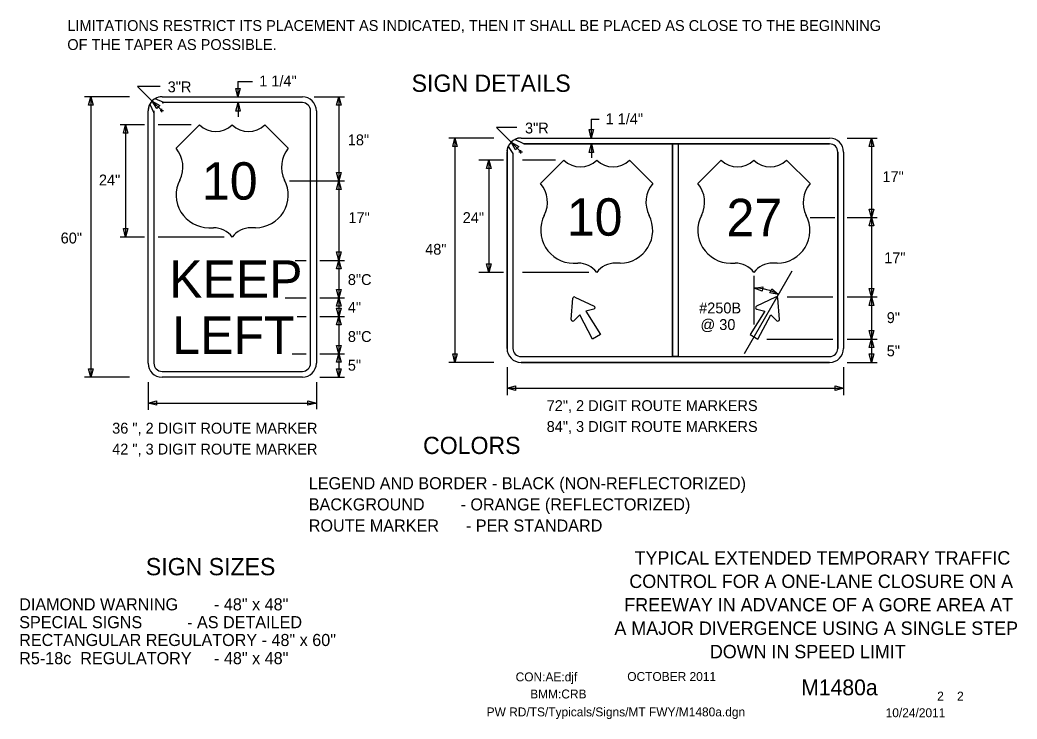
# Model space of a CAD drawing. Extents: x 16284 to 18468, y 5417 to 6974.
# Drawn here: x 17775 to 18468, y 5932 to 6418 of the extents above; entities that cross this region are included whole.
import ezdxf

# ---------------------------------------------------------------- set-up
doc = ezdxf.new("R2010")
doc.units = 0
for name, color, linetype in [('BORDER', 7, 'Continuous'), ('BORDER_SIGNAL_WO', 7, 'Continuous'), ('TRAFFIC_SIGNS_PR', 7, 'Continuous'), ('TYPICAL_EX', 7, 'Continuous'), ('TYPICAL_TEXT_DIMEN_PR', 7, 'Continuous')]:
    doc.layers.add(name, color=color, linetype=linetype)

msp = doc.modelspace()

# ---------------------------------------------------------------- linework, layer by layer
at = {"layer": 'TRAFFIC_SIGNS_PR'}
for p, q in [((17873.92, 6364.59), (17971.42, 6364.59)), ((17866.33, 6360.97), (17865.33, 6359.46)), ((17865.36, 6359.39), (17868.23, 6353.35)), ((17875.12, 6360.53), (17869.02, 6363.27)), ((17971.42, 6360.53), (17873.92, 6360.53)), ((17864.17, 6179.34), (17864.17, 6354.84)), ((17868.23, 6354.84), (17868.23, 6179.34)), ((17977.1, 6179.34), (17977.1, 6354.84)), ((17981.17, 6354.84), (17981.17, 6179.34)), ((18123.44, 6335.89), (18337.94, 6335.89)), ((18123.44, 6335.89), (18337.94, 6335.89)), ((18114.61, 6330.15), (18117.74, 6325.11)), ((18125.39, 6331.84), (18119.16, 6334.86)), ((18125.38, 6331.83), (18228.66, 6331.83)), ((18337.94, 6331.83), (18125.38, 6331.83)), ((18228.66, 6331.83), (18228.66, 6183.95)), ((18232.72, 6331.83), (18232.72, 6183.95)), ((18232.72, 6331.83), (18337.94, 6331.83)), ((18113.69, 6326.14), (18113.69, 6189.64)), ((18113.69, 6189.64), (18113.69, 6326.14)), ((18117.75, 6325.09), (18117.75, 6189.64)), ((18117.75, 6325.09), (18117.75, 6189.64)), ((18343.62, 6326.14), (18343.62, 6280.39)), ((18343.63, 6189.64), (18343.63, 6326.14)), ((18347.69, 6326.14), (18347.69, 6189.64)), ((18347.69, 6326.14), (18347.69, 6189.64)), ((18343.62, 6280.39), (18343.62, 6189.64)), ((18160.95, 6225.34), (18174.27, 6218.98)), ((18300.42, 6225.34), (18287.11, 6218.98)), ((18158.29, 6209.75), (18159.44, 6224.47)), ((18303.08, 6209.75), (18301.94, 6224.47)), ((18123.44, 6183.95), (18337.94, 6183.95)), ((18123.44, 6179.89), (18337.94, 6179.89)), ((18337.94, 6179.89), (18123.44, 6179.89)), ((17873.92, 6173.65), (17971.42, 6173.65)), ((17971.42, 6169.59), (17873.92, 6169.59))]:
    msp.add_line(p, q, dxfattribs=at)
for points in [[(18125.38, 6331.83), (18125.36, 6331.84)], [(18117.74, 6325.11), (18117.75, 6325.09)], [(18174.1, 6217.01), (18168.38, 6215.43), (18178.6, 6199.26), (18173.2, 6196.14), (18164.31, 6213.08), (18160.08, 6208.91)], [(18287.27, 6217.01), (18292.99, 6215.43), (18282.78, 6199.26), (18288.17, 6196.14), (18297.07, 6213.08), (18301.29, 6208.91)]]:
    msp.add_lwpolyline(points, dxfattribs=at)
msp.add_lwpolyline([(18228.66, 6331.83), (18232.72, 6331.83), (18232.72, 6183.95), (18228.66, 6183.95)], close=True, dxfattribs=at)
for centre, radius, start, end in [((17873.92, 6354.84), 9.75, 90, 180), ((17873.33, 6357.01), 7.6, 85.58319, 124.53531), ((17971.42, 6354.84), 9.75, 0, 90), ((17871.2, 6355.43), 7.06, 145.86811, 184.82317), ((17874.52, 6364.95), 4.47, 262.2432, 277.7568), ((17971.42, 6354.84), 5.69, 0, 90), ((17862.77, 6354.1), 5.51, 352.24294, 7.75653), ((18123.44, 6326.14), 9.75, 90, 180), ((18123.44, 6326.14), 9.75, 90, 180), ((18122.76, 6329.33), 6.6, 84.11162, 123.06374), ((18337.94, 6326.14), 9.75, 0, 90), ((18337.94, 6326.14), 9.75, 0, 90), ((18119.82, 6326.85), 6.17, 147.60925, 186.56283), ((18124.38, 6339.01), 7.24, 277.81035, 278.05403), ((18337.94, 6326.14), 5.69, 0, 89.99421), ((18337.94, 6326.14), 5.69, 0, 90), ((18160.5, 6224.38), 1.06, 64.48226, 175.51774), ((18300.88, 6224.38), 1.06, 4.48226, 115.51774), ((18173.81, 6218.02), 1.06, 285.9885, 64.48226), ((18287.56, 6218.02), 1.06, 115.51774, 254.0115), ((18159.35, 6209.67), 1.06, 175.51775, 314.01151), ((18302.03, 6209.67), 1.06, 225.98849, 4.48225), ((18123.44, 6189.64), 9.75, 180, 270), ((18123.44, 6189.64), 9.75, 180, 270), ((18123.44, 6189.64), 5.69, 180, 270), ((18123.44, 6189.64), 5.69, 180, 270), ((18337.94, 6189.64), 9.75, 270, 0), ((18337.94, 6189.64), 5.69, 270, 0), ((18337.94, 6189.64), 9.75, 270, 0), ((18337.94, 6189.64), 5.69, 270, 0), ((17873.92, 6179.34), 9.75, 180, 270), ((17873.92, 6179.34), 5.69, 180, 270), ((17971.42, 6179.34), 5.69, 270, 0), ((17971.42, 6179.34), 9.75, 270, 0)]:
    msp.add_arc(centre, radius, start, end, dxfattribs=at)
at = {"layer": 'TYPICAL_EX'}
for p, q in [((17883.67, 6328.84), (17899.92, 6345.09)), ((17961.67, 6328.84), (17945.42, 6345.09)), ((18137.05, 6304.23), (18153.3, 6320.48)), ((18215.05, 6304.23), (18198.8, 6320.48)), ((18246.33, 6304.23), (18262.58, 6320.48)), ((18324.33, 6304.23), (18308.08, 6320.48)), ((17906.39, 6273.55), (17909.64, 6273.55)), ((17938.94, 6273.55), (17935.69, 6273.55)), ((18159.78, 6248.94), (18163.03, 6248.94)), ((18192.32, 6248.94), (18189.07, 6248.94)), ((18269.05, 6248.94), (18272.3, 6248.94)), ((18301.6, 6248.94), (18298.35, 6248.94))]:
    msp.add_line(p, q, dxfattribs=at)
for centre, radius, start, end in [((17911.29, 6356.93), 16.42, 226.14041, 313.85958), ((17934.04, 6356.93), 16.42, 226.14042, 313.85959), ((17868.26, 6315.83), 20.16, 333.09768, 40.19361), ((17977.07, 6315.83), 20.16, 139.80639, 206.90233), ((18164.68, 6332.32), 16.42, 226.14041, 313.85958), ((18187.42, 6332.32), 16.42, 226.14042, 313.85959), ((18273.95, 6332.32), 16.42, 226.14041, 313.85958), ((18296.7, 6332.32), 16.42, 226.14042, 313.85959), ((17906.43, 6296.27), 22.73, 152.6698, 269.90132), ((17938.9, 6296.27), 22.73, 270.09868, 27.3302), ((18121.65, 6291.22), 20.16, 333.09768, 40.19361), ((18230.45, 6291.22), 20.16, 139.80639, 206.90233), ((18230.93, 6291.22), 20.16, 333.09768, 40.19361), ((18339.73, 6291.22), 20.16, 139.80639, 206.90233), ((18159.82, 6271.66), 22.73, 152.6698, 269.90132), ((18192.28, 6271.66), 22.73, 270.09868, 27.3302), ((18269.09, 6271.66), 22.73, 152.6698, 269.90132), ((18301.56, 6271.66), 22.73, 270.09868, 27.3302), ((17909.68, 6257.27), 16.28, 37.1038, 90.13853), ((17935.65, 6257.27), 16.28, 89.86147, 142.8962), ((18163.07, 6232.66), 16.28, 37.1038, 90.13853), ((18189.03, 6232.66), 16.28, 89.86147, 142.8962), ((18272.35, 6232.66), 16.28, 37.1038, 90.13853), ((18298.31, 6232.66), 16.28, 89.86147, 142.8962)]:
    msp.add_arc(centre, radius, start, end, dxfattribs=at)
at = {"layer": 'TYPICAL_TEXT_DIMEN_PR'}
for p, q in [((17872.54, 6371.87), (17856.88, 6371.87)), ((17856.88, 6371.87), (17867.12, 6361.64)), ((17926.64, 6364.59), (17925.07, 6370.45)), ((17925.07, 6370.45), (17926.64, 6370.45)), ((17926.64, 6375.35), (17926.64, 6364.59)), ((17926.64, 6375.35), (17936.74, 6375.35)), ((17926.64, 6370.45), (17928.21, 6370.45)), ((17928.21, 6370.45), (17926.64, 6364.59)), ((17851.34, 6364.59), (17820.04, 6364.59)), ((17822.81, 6358.73), (17824.38, 6364.59)), ((17824.38, 6364.59), (17824.38, 6169.59)), ((17824.38, 6364.59), (17825.95, 6358.73)), ((17979.71, 6364.59), (18000.67, 6364.59)), ((17995.2, 6358.73), (17996.77, 6364.59)), ((17996.77, 6364.59), (17996.77, 6306.09)), ((17996.77, 6364.59), (17998.34, 6358.73)), ((17824.38, 6358.73), (17822.81, 6358.73)), ((17825.95, 6358.73), (17824.38, 6358.73)), ((17867.12, 6361.64), (17873.67, 6355.08)), ((17870.15, 6356.38), (17867.12, 6361.64)), ((17867.12, 6361.64), (17872.37, 6358.6)), ((17871.26, 6357.49), (17870.15, 6356.38)), ((17872.37, 6358.6), (17871.26, 6357.49)), ((17925.12, 6354.67), (17926.69, 6360.53)), ((17926.69, 6360.53), (17926.69, 6350.78)), ((17926.69, 6360.53), (17928.26, 6354.67)), ((17996.77, 6358.73), (17995.2, 6358.73)), ((17998.34, 6358.73), (17996.77, 6358.73)), ((17872.47, 6355.08), (17874.88, 6355.08)), ((17873.67, 6353.87), (17873.67, 6356.29)), ((17926.69, 6354.67), (17925.12, 6354.67)), ((17928.26, 6354.67), (17926.69, 6354.67)), ((17861.79, 6345.09), (17844.67, 6345.09)), ((17846.99, 6339.23), (17848.56, 6345.09)), ((17848.56, 6345.09), (17848.56, 6267.09)), ((17848.56, 6345.09), (17850.13, 6339.23)), ((17894.03, 6345.09), (17871.16, 6345.09)), ((18120.58, 6343.18), (18106.4, 6343.18)), ((18106.4, 6343.18), (18116.55, 6333.03)), ((18172.3, 6349.04), (18172.3, 6335.89)), ((18172.3, 6349.04), (18177.82, 6349.04)), ((17848.56, 6339.23), (17846.99, 6339.23)), ((17850.13, 6339.23), (17848.56, 6339.23)), ((18104.46, 6335.89), (18073.16, 6335.89)), ((18075.93, 6330.03), (18077.5, 6335.89)), ((18077.5, 6335.89), (18077.5, 6179.89)), ((18077.5, 6335.89), (18079.07, 6330.03)), ((18172.3, 6335.89), (18170.72, 6341.75)), ((18170.72, 6341.75), (18172.3, 6341.75)), ((18172.3, 6341.75), (18173.87, 6341.75)), ((18173.87, 6341.75), (18172.3, 6335.89)), ((18350.06, 6335.89), (18371.02, 6335.89)), ((18365.55, 6330.03), (18367.12, 6335.89)), ((18367.12, 6335.89), (18367.12, 6280.64)), ((18367.12, 6335.89), (18368.69, 6330.03)), ((18077.5, 6330.03), (18075.93, 6330.03)), ((18079.07, 6330.03), (18077.5, 6330.03)), ((18116.55, 6333.03), (18123.2, 6326.38)), ((18119.58, 6327.77), (18116.55, 6333.03)), ((18116.55, 6333.03), (18121.81, 6329.99)), ((18120.7, 6328.88), (18119.58, 6327.77)), ((18121.81, 6329.99), (18120.7, 6328.88)), ((18170.77, 6325.97), (18172.34, 6331.83)), ((18170.77, 6325.97), (18172.34, 6331.83)), ((18172.34, 6331.83), (18172.34, 6322.08)), ((18172.34, 6331.83), (18173.92, 6325.97)), ((18172.34, 6331.83), (18173.92, 6325.97)), ((18367.12, 6330.03), (18365.55, 6330.03)), ((18368.69, 6330.03), (18367.12, 6330.03)), ((18121.99, 6326.38), (18124.41, 6326.38)), ((18123.2, 6325.17), (18123.2, 6327.59)), ((18172.34, 6325.97), (18170.77, 6325.97)), ((18172.34, 6325.97), (18170.77, 6325.97)), ((18173.92, 6325.97), (18172.34, 6325.97)), ((18173.92, 6325.97), (18172.34, 6325.97)), ((18111.31, 6320.48), (18094.19, 6320.48)), ((18099.48, 6314.62), (18101.06, 6320.48)), ((18101.06, 6320.48), (18101.06, 6242.48)), ((18101.06, 6320.48), (18102.63, 6314.62)), ((18147.42, 6320.48), (18124.54, 6320.48)), ((17996.77, 6306.09), (17995.2, 6311.95)), ((17995.2, 6311.95), (17996.77, 6311.95)), ((17996.77, 6311.95), (17998.34, 6311.95)), ((17998.34, 6311.95), (17996.77, 6306.09)), ((18101.06, 6314.62), (18099.48, 6314.62)), ((18102.63, 6314.62), (18101.06, 6314.62)), ((17962.56, 6306.09), (18000.67, 6306.09)), ((17995.2, 6300.23), (17996.77, 6306.09)), ((17996.77, 6306.09), (17996.77, 6250.84)), ((17996.77, 6306.09), (17998.34, 6300.23)), ((17996.77, 6300.23), (17995.2, 6300.23)), ((17998.34, 6300.23), (17996.77, 6300.23)), ((18324.5, 6280.64), (18341.65, 6280.64)), ((18350.06, 6280.64), (18371.02, 6280.64)), ((18367.12, 6280.64), (18365.55, 6286.5)), ((18365.55, 6286.5), (18367.12, 6286.5)), ((18365.55, 6274.78), (18367.12, 6280.64)), ((18367.12, 6286.5), (18368.69, 6286.5)), ((18368.69, 6286.5), (18367.12, 6280.64)), ((18367.12, 6280.64), (18367.12, 6225.39)), ((18367.12, 6280.64), (18368.69, 6274.78)), ((18367.12, 6274.78), (18365.55, 6274.78)), ((18368.69, 6274.78), (18367.12, 6274.78)), ((17861.79, 6267.09), (17844.67, 6267.09)), ((17848.56, 6267.09), (17846.99, 6272.95)), ((17846.99, 6272.95), (17848.56, 6272.95)), ((17848.56, 6272.95), (17850.13, 6272.95)), ((17850.13, 6272.95), (17848.56, 6267.09)), ((17917.16, 6267.09), (17871.16, 6267.09)), ((17996.77, 6250.84), (17995.2, 6256.7)), ((17995.2, 6256.7), (17996.77, 6256.7)), ((17996.77, 6256.7), (17998.34, 6256.7)), ((17998.34, 6256.7), (17996.77, 6250.84)), ((17966.49, 6250.84), (17974.17, 6250.84)), ((17983.54, 6250.84), (18000.67, 6250.84)), ((17995.2, 6244.98), (17996.77, 6250.84)), ((17996.77, 6250.84), (17996.77, 6224.84)), ((17996.77, 6250.84), (17998.34, 6244.98)), ((18101.06, 6242.48), (18099.48, 6248.34)), ((18099.48, 6248.34), (18101.06, 6248.34)), ((18101.06, 6248.34), (18102.63, 6248.34)), ((18102.63, 6248.34), (18101.06, 6242.48)), ((17996.77, 6244.98), (17995.2, 6244.98)), ((17998.34, 6244.98), (17996.77, 6244.98)), ((18111.31, 6242.48), (18094.19, 6242.48)), ((18170.54, 6242.48), (18124.54, 6242.48)), ((18278.72, 6185.99), (18311.96, 6243.58)), ((18285.48, 6206.15), (18285.48, 6240.14)), ((18285.51, 6231.59), (18291.5, 6232.55)), ((18291.5, 6232.55), (18291.34, 6230.98)), ((17959.48, 6224.84), (17974.17, 6224.84)), ((17983.54, 6224.84), (18000.67, 6224.84)), ((17996.77, 6224.84), (17995.2, 6230.7)), ((17995.2, 6230.7), (17996.77, 6230.7)), ((17995.2, 6218.98), (17996.77, 6224.84)), ((17996.77, 6230.7), (17998.34, 6230.7)), ((17998.34, 6230.7), (17996.77, 6224.84)), ((17996.77, 6224.84), (17996.77, 6211.84)), ((17996.77, 6224.84), (17998.34, 6218.98)), ((18291.17, 6229.42), (18285.51, 6231.59)), ((18291.34, 6230.98), (18291.17, 6229.42)), ((18296.49, 6228.26), (18297.17, 6229.68)), ((18302.46, 6227.13), (18296.49, 6228.26)), ((18297.17, 6229.68), (18297.86, 6231.09)), ((18297.86, 6231.09), (18302.46, 6227.13)), ((18308.43, 6225.39), (18340.3, 6225.39)), ((18350.06, 6225.39), (18371.02, 6225.39)), ((18367.12, 6225.39), (18365.55, 6231.25)), ((18365.55, 6231.25), (18367.12, 6231.25)), ((18365.55, 6219.53), (18367.12, 6225.39)), ((18367.12, 6231.25), (18368.69, 6231.25)), ((18368.69, 6231.25), (18367.12, 6225.39)), ((18367.12, 6225.39), (18367.12, 6196.14)), ((18367.12, 6225.39), (18368.69, 6219.53)), ((17996.77, 6218.98), (17995.2, 6218.98)), ((17998.34, 6218.98), (17996.77, 6218.98)), ((18367.12, 6219.53), (18365.55, 6219.53)), ((18368.69, 6219.53), (18367.12, 6219.53)), ((17967.83, 6211.84), (17974.17, 6211.84)), ((17983.54, 6211.84), (18000.67, 6211.84)), ((17996.77, 6211.84), (17995.2, 6217.7)), ((17995.2, 6217.7), (17996.77, 6217.7)), ((17995.2, 6205.98), (17996.77, 6211.84)), ((17996.77, 6217.7), (17998.34, 6217.7)), ((17998.34, 6217.7), (17996.77, 6211.84)), ((17996.77, 6211.84), (17996.77, 6185.84)), ((17996.77, 6211.84), (17998.34, 6205.98)), ((17996.77, 6205.98), (17995.2, 6205.98)), ((17998.34, 6205.98), (17996.77, 6205.98)), ((18367.12, 6196.14), (18365.55, 6202)), ((18365.55, 6202), (18367.12, 6202)), ((18367.12, 6202), (18368.69, 6202)), ((18368.69, 6202), (18367.12, 6196.14)), ((17996.77, 6185.84), (17995.2, 6191.7)), ((17995.2, 6191.7), (17996.77, 6191.7)), ((17996.77, 6191.7), (17998.34, 6191.7)), ((17998.34, 6191.7), (17996.77, 6185.84)), ((18294.29, 6196.14), (18340.3, 6196.14)), ((18350.06, 6196.14), (18371.02, 6196.14)), ((18365.55, 6190.28), (18367.12, 6196.14)), ((18367.12, 6190.28), (18365.55, 6190.28)), ((18367.12, 6196.14), (18367.12, 6179.89)), ((18367.12, 6196.14), (18368.69, 6190.28)), ((18368.69, 6190.28), (18367.12, 6190.28)), ((17964.33, 6185.84), (17974.17, 6185.84)), ((17983.54, 6185.84), (18000.67, 6185.84)), ((17995.2, 6179.98), (17996.77, 6185.84)), ((17996.77, 6185.84), (17996.77, 6169.59)), ((17996.77, 6185.84), (17998.34, 6179.98)), ((18077.5, 6179.89), (18075.93, 6185.75)), ((18075.93, 6185.75), (18077.5, 6185.75)), ((18077.5, 6185.75), (18079.07, 6185.75)), ((18079.07, 6185.75), (18077.5, 6179.89)), ((18367.12, 6179.89), (18365.55, 6185.75)), ((18365.55, 6185.75), (18367.12, 6185.75)), ((18367.12, 6185.75), (18368.69, 6185.75)), ((18368.69, 6185.75), (18367.12, 6179.89)), ((17996.77, 6179.98), (17995.2, 6179.98)), ((17998.34, 6179.98), (17996.77, 6179.98)), ((18104.46, 6179.89), (18073.16, 6179.89)), ((18113.69, 6176.55), (18113.69, 6156.99)), ((18347.69, 6176.55), (18347.69, 6156.99)), ((18350.06, 6179.89), (18367.19, 6179.89)), ((18350.06, 6179.89), (18371.02, 6179.89)), ((18350.06, 6179.89), (18367.19, 6179.89)), ((17851.34, 6169.59), (17820.04, 6169.59)), ((17824.38, 6169.59), (17822.81, 6175.45)), ((17822.81, 6175.45), (17824.38, 6175.45)), ((17824.38, 6175.45), (17825.95, 6175.45)), ((17825.95, 6175.45), (17824.38, 6169.59)), ((17983.54, 6169.59), (18000.67, 6169.59)), ((17996.77, 6169.59), (17995.2, 6175.45)), ((17995.2, 6175.45), (17996.77, 6175.45)), ((17996.77, 6175.45), (17998.34, 6175.45)), ((17998.34, 6175.45), (17996.77, 6169.59)), ((17864.17, 6166.25), (17864.17, 6146.89)), ((17981.17, 6166.25), (17981.17, 6147.35)), ((18113.69, 6161.92), (18119.55, 6163.49)), ((18119.55, 6163.49), (18119.55, 6161.92)), ((18341.83, 6161.92), (18341.83, 6163.49)), ((18341.83, 6163.49), (18347.69, 6161.92)), ((18113.69, 6161.92), (18347.69, 6161.92)), ((18119.55, 6160.35), (18113.69, 6161.92)), ((18119.55, 6161.92), (18119.55, 6160.35)), ((18347.69, 6161.92), (18341.83, 6160.35)), ((18341.83, 6160.35), (18341.83, 6161.92)), ((17864.17, 6151.62), (17870.03, 6153.19)), ((17864.17, 6151.62), (17981.17, 6151.62)), ((17870.03, 6150.05), (17864.17, 6151.62)), ((17870.03, 6153.19), (17870.03, 6151.62)), ((17870.03, 6151.62), (17870.03, 6150.05)), ((17975.3, 6151.62), (17975.3, 6153.19)), ((17975.3, 6153.19), (17981.17, 6151.62)), ((17981.17, 6151.62), (17975.3, 6150.05)), ((17975.3, 6150.05), (17975.3, 6151.62))]:
    msp.add_line(p, q, dxfattribs=at)
msp.add_arc((18285.67, 6197.15), 34.39, 60.74521, 90.32117, dxfattribs=at)

# ---------------------------------------------------------------- texts
at = {"layer": 'BORDER'}
for s, p in [('TYPICAL EXTENDED TEMPORARY TRAFFIC', (18202.37, 6039.3)), ('CONTROL FOR A ONE-LANE CLOSURE ON A', (18198.74, 6023)), ('FREEWAY IN ADVANCE OF A GORE AREA AT', (18195.24, 6006.7)), ('A MAJOR DIVERGENCE USING A SINGLE STEP', (18188.37, 5990.4)), ('DOWN IN SPEED LIMIT', (18254.74, 5974.11))]:
    msp.add_text(s, height=9.3, dxfattribs=at).set_placement(p)
at = {"layer": 'BORDER_SIGNAL_WO'}
for s, height, p in [('CON:AE:djf  ', 6.2, (18119.69, 5958.06)), ('    OCTOBER 2011    ', 6.2, (18188.08, 5958.34)), ('    M1480a   ', 11, (18301.86, 5948.38)), ('BMM:CRB   ', 6.2, (18129.81, 5946.17)), (' 2    2 ', 6.2, (18410.45, 5944.7)), ('PW RD/TS/Typicals/Signs/MT FWY/M1480a.dgn      ', 6.2, (18099.55, 5933.71)), ('10/24/2011    ', 6.2, (18376.93, 5933.13))]:
    msp.add_text(s, height=height, dxfattribs=at).set_placement(p)
at = {"layer": 'TRAFFIC_SIGNS_PR'}
for s, p in [('10', (17901.64, 6293.09)), ('10', (18155.29, 6268.02)), ('27', (18266.29, 6267.66)), ('KEEP', (17878.77, 6224.84)), ('LEFT', (17881, 6185.84))]:
    msp.add_text(s, height=26, dxfattribs=at).set_placement(p)
at = {"layer": 'TYPICAL_TEXT_DIMEN_PR'}
for s, height, p in [('LIMITATIONS RESTRICT ITS PLACEMENT AS INDICATED, THEN IT SHALL BE PLACED AS CLOSE TO THE BEGINNING', 7.56, (17808.03, 6410.38)), ('OF THE TAPER AS POSSIBLE.', 7.56, (17808.03, 6397.15)), ('1 1/4"', 7.55, (17941.44, 6371.85)), ('SIGN DETAILS', 12, (18047.39, 6368.06)), ('3"R', 7.55, (17877.8, 6367.75)), ('1 1/4"', 7.55, (18182.22, 6345.47)), ('3"R', 7.55, (18126.22, 6339.1)), ('18"', 7.55, (18003.01, 6330.86)), ('24"', 7.55, (17830.01, 6302.97)), ('17"', 7.55, (18374.7, 6305.25)), ('17"', 7.55, (18003.46, 6276.81)), ('24"', 7.55, (18082.91, 6276.81)), ('60"', 7.55, (17803.41, 6262.61)), ('48"', 7.55, (18056.8, 6254.79)), ('17"', 7.55, (18375.9, 6248.89)), ('8"C', 7.55, (18003.04, 6233.7)), ('4" ', 7.55, (18003.04, 6214.44)), ('#250B', 7.55, (18247.25, 6213.98)), ('9"', 7.55, (18377.68, 6207.24)), ('@ 30', 7.55, (18248.19, 6202.43)), ('8"C', 7.55, (18003.04, 6194.11)), ('5"', 7.55, (18377.68, 6184.14)), ('5" ', 7.55, (18003.04, 6174.14)), ('72", 2 DIGIT ROUTE MARKERS', 7.55, (18141.27, 6146.06)), ('36 ", 2 DIGIT ROUTE MARKER', 7.55, (17839.21, 6130.36)), ('84", 3 DIGIT ROUTE MARKERS', 7.55, (18141.27, 6131.51)), ('COLORS', 12, (18055.33, 6116.17)), ('42 ", 3 DIGIT ROUTE MARKER', 7.55, (17839.21, 6115.81)), ('LEGEND AND BORDER - BLACK (NON-REFLECTORIZED)', 8.4, (17975.9, 6091.65)), ('BACKGROUND        - ORANGE (REFLECTORIZED)', 8.4, (17975.9, 6076.94)), ('ROUTE MARKER      - PER STANDARD', 8.4, (17975.9, 6062.24)), ('SIGN SIZES', 12, (17862.62, 6031.84)), ('DIAMOND WARNING        - 48" x 48"', 8.4, (17774.58, 6007.44)), ('SPECIAL SIGNS          - AS DETAILED', 8.4, (17774.58, 5995.04)), ('RECTANGULAR REGULATORY - 48" x 60"', 8.4, (17774.58, 5982.64)), ('R5-18c  REGULATORY     - 48" x 48"', 8.4, (17774.58, 5969.99))]:
    msp.add_text(s, height=height, dxfattribs=at).set_placement(p)

doc.saveas('drawing.dxf')
